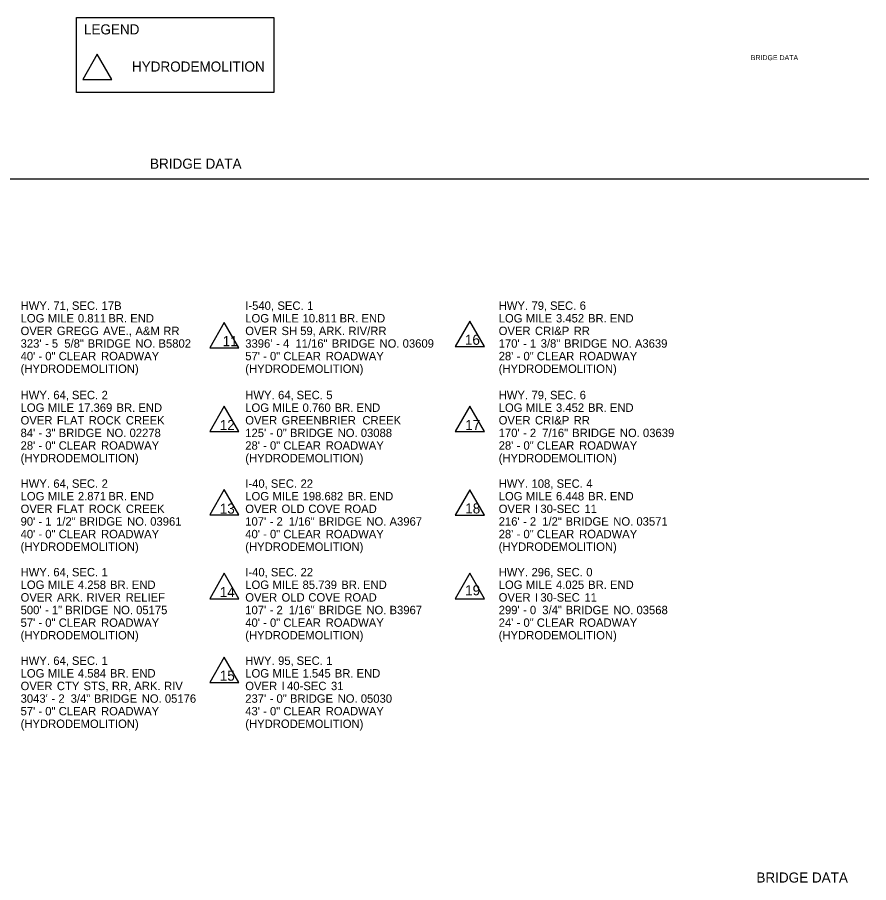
# Model space of a CAD drawing. Extents: x 1930579 to 1935271, y 596413 to 597442.
# Drawn here: x 1934259 to 1935271, y 596413 to 597442 of the extents above; entities that cross this region are included whole.
import ezdxf

# ---------------------------------------------------------------- set-up
doc = ezdxf.new("R2010")
doc.units = 0
for name, color, linetype in [('Default', 7, 'Continuous'), ('R_Border', 7, 'Continuous'), ('R_Border Prem', 7, 'Continuous')]:
    doc.layers.add(name, color=color, linetype=linetype)

msp = doc.modelspace()

# ---------------------------------------------------------------- linework, layer by layer
at = {"layer": 'R_Border'}
for p, q in [((1934353.7, 597398.8), (1934336.3, 597368.6)), ((1934371.1, 597368.6), (1934353.7, 597398.8)), ((1934336.3, 597368.6), (1934371.1, 597368.6)), ((1935270.8, 597250), (1933675.4, 597250)), ((1934504.7, 597079.6), (1934487.3, 597049.4)), ((1934522.1, 597049.4), (1934504.7, 597079.6)), ((1934796.4, 597081.3), (1934779, 597051.1)), ((1934813.9, 597051.1), (1934796.4, 597081.3)), ((1934487.3, 597049.4), (1934522.1, 597049.4)), ((1934779, 597051.1), (1934813.9, 597051.1)), ((1934504.7, 596980), (1934487.3, 596949.9)), ((1934522.1, 596949.9), (1934504.7, 596980)), ((1934796.4, 596980), (1934779, 596949.8)), ((1934813.9, 596949.8), (1934796.4, 596980)), ((1934487.3, 596949.9), (1934522.1, 596949.9)), ((1934779, 596949.8), (1934813.9, 596949.8)), ((1934504.7, 596880.8), (1934487.3, 596850.7)), ((1934522.1, 596850.7), (1934504.7, 596880.8)), ((1934796.4, 596880.7), (1934779, 596850.5)), ((1934813.9, 596850.5), (1934796.4, 596880.7)), ((1934487.3, 596850.7), (1934522.1, 596850.7)), ((1934779, 596850.5), (1934813.9, 596850.5)), ((1934504.7, 596781.3), (1934487.3, 596751.1)), ((1934522.1, 596751.1), (1934504.7, 596781.3)), ((1934796.4, 596781.3), (1934779, 596751.1)), ((1934813.9, 596751.1), (1934796.4, 596781.3)), ((1934487.3, 596751.1), (1934522.1, 596751.1)), ((1934779, 596751.1), (1934813.9, 596751.1)), ((1934504.7, 596681.8), (1934487.3, 596651.6)), ((1934522.1, 596651.6), (1934504.7, 596681.8)), ((1934487.3, 596651.6), (1934522.1, 596651.6))]:
    msp.add_line(p, q, dxfattribs=at)
msp.add_lwpolyline([(1934329, 597442.4), (1934563.4, 597442.4), (1934563.4, 597353.2), (1934329, 597353.2)], close=True, dxfattribs=at)

# ---------------------------------------------------------------- texts
at = {"layer": 'Default'}
for s, p in [('HWY.', (1934262.5, 597094.6)), (' 71,', (1934297.7, 597094.6)), (' SEC.', (1934319.8, 597094.6)), (' 17B', (1934355.1, 597094.6)), ('I-540,', (1934529.6, 597094.6)), (' SEC.', (1934564.1, 597094.6)), (' 1', (1934599.4, 597094.6)), ('HWY.', (1934830.9, 597094.6)), (' 79,', (1934866.2, 597094.6)), (' SEC.', (1934888.2, 597094.6)), (' 6', (1934923.5, 597094.6)), ('LOG', (1934262.5, 597079.6)), (' MILE', (1934291.1, 597079.6)), (' 0.811', (1934326.9, 597079.6)), (' BR.', (1934363.1, 597079.6)), (' END', (1934389.1, 597079.6)), ('LOG', (1934529.6, 597079.6)), (' MILE', (1934558.3, 597079.6)), (' 10.811', (1934594, 597079.6)), (' BR.', (1934638, 597079.6)), (' END', (1934664, 597079.6)), ('LOG', (1934830.9, 597079.6)), (' MILE', (1934859.5, 597079.6)), (' 3.452', (1934895.3, 597079.6)), (' BR.', (1934933.4, 597079.6)), (' END', (1934959.3, 597079.6)), ('OVER', (1934262.5, 597064.6)), (' GREGG', (1934301.9, 597064.6)), (' AVE.,', (1934356.9, 597064.6)), (' A&M', (1934395.3, 597064.6)), (' RR', (1934428.4, 597064.6)), ('OVER', (1934529.6, 597064.6)), (' SH', (1934569, 597064.6)), (' 59,', (1934591.2, 597064.6)), (' ARK.', (1934613.3, 597064.6)), (' RIV/RR', (1934648.5, 597064.6)), ('OVER', (1934830.9, 597064.6)), (' CRI&P', (1934870.3, 597064.6)), (' RR', (1934916.3, 597064.6)), ("323'", (1934262.5, 597049.6)), (' 5', (1934295.9, 597049.6)), ('  5/8"', (1934307, 597049.6)), (' BRIDGE', (1934338.5, 597049.6)), (' NO.', (1934395.2, 597049.6)), (' B5802', (1934422.7, 597049.6)), ("3396'", (1934529.6, 597049.6)), (' 4', (1934570.8, 597049.6)), ('  11/16"', (1934581.8, 597049.6)), (' BRIDGE', (1934628.8, 597049.6)), (' NO.', (1934685.5, 597049.6)), (' 03609', (1934713, 597049.6)), ("170'", (1934830.9, 597049.6)), (' 1', (1934864.3, 597049.6)), ('  3/8"', (1934873.4, 597049.6)), (' BRIDGE', (1934904.9, 597049.6)), (' NO.', (1934961.6, 597049.6)), (' A3639', (1934989.1, 597049.6)), (' -', (1934287.8, 597049.6)), (' -', (1934562.7, 597049.6)), (' -', (1934856.2, 597049.6)), ("40'", (1934262.5, 597034.6)), (' -', (1934280, 597034.6)), (' 0"', (1934288.1, 597034.6)), (' CLEAR', (1934304.1, 597034.6)), (' ROADWAY', (1934354.4, 597034.6)), ("57'", (1934529.6, 597034.6)), (' -', (1934547.2, 597034.6)), (' 0"', (1934555.3, 597034.6)), (' CLEAR', (1934571.2, 597034.6)), (' ROADWAY', (1934621.5, 597034.6)), ("28'", (1934830.9, 597034.6)), (' -', (1934848.5, 597034.6)), (' 0"', (1934856.6, 597034.6)), (' CLEAR', (1934872.5, 597034.6)), (' ROADWAY', (1934922.8, 597034.6)), ('(HYDRODEMOLITION)', (1934262.5, 597019.6)), ('(HYDRODEMOLITION)', (1934529.6, 597019.6)), ('(HYDRODEMOLITION)', (1934830.9, 597019.6)), ('HWY.', (1934262.5, 596988.3)), (' 64,', (1934297.7, 596988.3)), (' SEC.', (1934319.8, 596988.3)), (' 2', (1934355.1, 596988.3)), ('HWY.', (1934529.6, 596988.3)), (' 64,', (1934564.9, 596988.3)), (' SEC.', (1934586.9, 596988.3)), (' 5', (1934622.2, 596988.3)), ('HWY.', (1934830.9, 596988.3)), (' 79,', (1934866.2, 596988.3)), (' SEC.', (1934888.2, 596988.3)), (' 6', (1934923.5, 596988.3)), ('LOG', (1934262.5, 596973.3)), (' MILE', (1934291.1, 596973.3)), (' 17.369', (1934326.9, 596973.3)), (' BR.', (1934372.8, 596973.3)), (' END', (1934398.8, 596973.3)), ('LOG', (1934529.6, 596973.3)), (' MILE', (1934558.3, 596973.3)), (' 0.760', (1934594, 596973.3)), (' BR.', (1934632.2, 596973.3)), (' END', (1934658.1, 596973.3)), ('LOG', (1934830.9, 596973.3)), (' MILE', (1934859.5, 596973.3)), (' 3.452', (1934895.3, 596973.3)), (' BR.', (1934933.4, 596973.3)), (' END', (1934959.3, 596973.3)), ('OVER', (1934262.5, 596958.3)), (' FLAT', (1934301.9, 596958.3)), (' ROCK', (1934339.7, 596958.3)), (' CREEK', (1934383.9, 596958.3)), ('OVER', (1934529.6, 596958.3)), (' GREENBRIER', (1934569, 596958.3)), (' CREEK', (1934665.1, 596958.3)), ('OVER', (1934830.9, 596958.3)), (' CRI&P', (1934870.3, 596958.3)), (' RR', (1934916.3, 596958.3)), ("84'", (1934262.5, 596943.3)), (' -', (1934280, 596943.3)), (' 3"', (1934288.1, 596943.3)), (' BRIDGE', (1934304.1, 596943.3)), (' NO.', (1934360.8, 596943.3)), (' 02278', (1934388.3, 596943.3)), ("125'", (1934529.6, 596943.3)), (' -', (1934554.9, 596943.3)), (' 0"', (1934563, 596943.3)), (' BRIDGE', (1934579, 596943.3)), (' NO.', (1934635.7, 596943.3)), (' 03088', (1934663.2, 596943.3)), ("170'", (1934830.9, 596943.3)), (' -', (1934856.2, 596943.3)), (' 2', (1934864.3, 596943.3)), ('  7/16"', (1934875.2, 596943.3)), (' BRIDGE', (1934914.5, 596943.3)), (' NO.', (1934971.2, 596943.3)), (' 03639', (1934998.7, 596943.3)), ("28'", (1934262.5, 596928.3)), (' 0"', (1934288.1, 596928.3)), (' CLEAR', (1934304.1, 596928.3)), (' ROADWAY', (1934354.4, 596928.3)), ("28'", (1934529.6, 596928.3)), (' 0"', (1934555.3, 596928.3)), (' CLEAR', (1934571.2, 596928.3)), (' ROADWAY', (1934621.5, 596928.3)), ("28'", (1934830.9, 596928.3)), (' 0"', (1934856.6, 596928.3)), (' CLEAR', (1934872.5, 596928.3)), (' ROADWAY', (1934922.8, 596928.3)), (' -', (1934280, 596928.3)), (' -', (1934547.2, 596928.3)), (' -', (1934848.5, 596928.3)), ('(HYDRODEMOLITION)', (1934262.5, 596913.3)), ('(HYDRODEMOLITION)', (1934529.6, 596913.3)), ('(HYDRODEMOLITION)', (1934830.9, 596913.3)), ('HWY.', (1934262.5, 596883)), (' 64,', (1934297.7, 596883)), (' SEC.', (1934319.8, 596883)), (' 2', (1934355.1, 596883)), ('I-40,', (1934529.6, 596883)), (' SEC.', (1934556.3, 596883)), (' 22', (1934591.6, 596883)), ('HWY.', (1934830.9, 596883)), (' 108,', (1934866.2, 596883)), (' SEC.', (1934896, 596883)), (' 4', (1934931.3, 596883)), ('LOG', (1934262.5, 596868)), (' MILE', (1934291.1, 596868)), (' 2.871', (1934326.9, 596868)), (' BR.', (1934363.1, 596868)), (' END', (1934389.1, 596868)), ('LOG', (1934529.6, 596868)), (' MILE', (1934558.3, 596868)), (' 198.682', (1934594, 596868)), (' BR.', (1934647.6, 596868)), (' END', (1934673.6, 596868)), ('LOG', (1934830.9, 596868)), (' MILE', (1934859.5, 596868)), (' 6.448', (1934895.3, 596868)), (' BR.', (1934933.5, 596868)), (' END', (1934959.4, 596868)), ('OVER', (1934262.5, 596853)), (' FLAT', (1934301.9, 596853)), (' ROCK', (1934339.7, 596853)), (' CREEK', (1934383.9, 596853)), ('OVER', (1934529.6, 596853)), (' OLD', (1934569, 596853)), (' COVE', (1934600.9, 596853)), (' ROAD', (1934643.6, 596853)), ('OVER', (1934830.9, 596853)), (' I', (1934870.3, 596853)), (' 30-SEC', (1934876.8, 596853)), (' 11', (1934929.1, 596853)), ("90'", (1934262.5, 596838)), (' -', (1934280, 596838)), (' 1', (1934288.1, 596838)), ('  1/2"', (1934297.2, 596838)), (' BRIDGE', (1934328.7, 596838)), (' NO.', (1934385.4, 596838)), (' 03961', (1934412.9, 596838)), ("107'", (1934529.6, 596838)), (' -', (1934554.9, 596838)), (' 2', (1934563, 596838)), ('  1/16"', (1934573.9, 596838)), (' BRIDGE', (1934613.2, 596838)), (' NO.', (1934669.9, 596838)), (' A3967', (1934697.4, 596838)), ("216'", (1934830.9, 596838)), (' -', (1934856.2, 596838)), (' 2', (1934864.3, 596838)), ('  1/2"', (1934875.2, 596838)), (' BRIDGE', (1934906.7, 596838)), (' NO.', (1934963.4, 596838)), (' 03571', (1934990.9, 596838)), ("40'", (1934262.5, 596823)), (' 0"', (1934288.1, 596823)), (' CLEAR', (1934304.1, 596823)), (' ROADWAY', (1934354.4, 596823)), ("40'", (1934529.6, 596823)), (' 0"', (1934555.3, 596823)), (' CLEAR', (1934571.2, 596823)), (' ROADWAY', (1934621.5, 596823)), ("28'", (1934830.9, 596823)), (' 0"', (1934856.6, 596823)), (' CLEAR', (1934872.5, 596823)), (' ROADWAY', (1934922.8, 596823)), (' -', (1934280, 596823)), (' -', (1934547.2, 596823)), (' -', (1934848.5, 596823)), ('(HYDRODEMOLITION)', (1934262.5, 596808)), ('(HYDRODEMOLITION)', (1934529.6, 596808)), ('(HYDRODEMOLITION)', (1934830.9, 596808)), ('HWY.', (1934262.5, 596777.7)), (' 64,', (1934297.7, 596777.7)), (' SEC.', (1934319.8, 596777.7)), (' 1', (1934355.1, 596777.7)), ('I-40,', (1934529.6, 596777.7)), (' SEC.', (1934556.3, 596777.7)), (' 22', (1934591.6, 596777.7)), ('HWY.', (1934830.9, 596777.7)), (' 296,', (1934866.2, 596777.7)), (' SEC.', (1934896, 596777.7)), (' 0', (1934931.3, 596777.7)), ('LOG', (1934262.5, 596762.7)), (' MILE', (1934291.1, 596762.7)), (' 4.258', (1934326.9, 596762.7)), (' BR.', (1934365.1, 596762.7)), (' END', (1934391, 596762.7)), ('LOG', (1934529.6, 596762.7)), (' MILE', (1934558.3, 596762.7)), (' 85.739', (1934594, 596762.7)), (' BR.', (1934640, 596762.7)), (' END', (1934665.9, 596762.7)), ('LOG', (1934830.9, 596762.7)), (' MILE', (1934859.5, 596762.7)), (' 4.025', (1934895.3, 596762.7)), (' BR.', (1934933.5, 596762.7)), (' END', (1934959.5, 596762.7)), ('OVER', (1934262.5, 596747.7)), (' ARK.', (1934301.9, 596747.7)), (' RIVER', (1934337.2, 596747.7)), (' RELIEF', (1934383.6, 596747.7)), ('OVER', (1934529.6, 596747.7)), (' OLD', (1934569, 596747.7)), (' COVE', (1934600.9, 596747.7)), (' ROAD', (1934643.6, 596747.7)), ('OVER', (1934830.9, 596747.7)), (' I', (1934870.3, 596747.7)), (' 30-SEC', (1934876.8, 596747.7)), (' 11', (1934929.1, 596747.7)), ("500'", (1934262.5, 596732.7)), (' 1"', (1934295.9, 596732.7)), (' BRIDGE', (1934311.8, 596732.7)), (' NO.', (1934368.6, 596732.7)), (' 05175', (1934396.1, 596732.7)), ("107'", (1934529.6, 596732.7)), (' 2', (1934563, 596732.7)), ('  1/16"', (1934573.9, 596732.7)), (' BRIDGE', (1934613.2, 596732.7)), (' NO.', (1934669.9, 596732.7)), (' B3967', (1934697.4, 596732.7)), ("299'", (1934830.9, 596732.7)), (' 0', (1934864.3, 596732.7)), ('  3/4"', (1934875.3, 596732.7)), (' BRIDGE', (1934906.8, 596732.7)), (' NO.', (1934963.5, 596732.7)), (' 03568', (1934991, 596732.7)), (' -', (1934287.8, 596732.7)), (' -', (1934554.9, 596732.7)), (' -', (1934856.2, 596732.7)), ("57'", (1934262.5, 596717.7)), (' -', (1934280, 596717.7)), (' 0"', (1934288.1, 596717.7)), (' CLEAR', (1934304.1, 596717.7)), (' ROADWAY', (1934354.4, 596717.7)), ("40'", (1934529.6, 596717.7)), (' -', (1934547.2, 596717.7)), (' 0"', (1934555.3, 596717.7)), (' CLEAR', (1934571.2, 596717.7)), (' ROADWAY', (1934621.5, 596717.7)), ("24'", (1934830.9, 596717.7)), (' -', (1934848.5, 596717.7)), (' 0"', (1934856.6, 596717.7)), (' CLEAR', (1934872.5, 596717.7)), (' ROADWAY', (1934922.8, 596717.7)), ('(HYDRODEMOLITION)', (1934262.5, 596702.7)), ('(HYDRODEMOLITION)', (1934529.6, 596702.7)), ('(HYDRODEMOLITION)', (1934830.9, 596702.7)), ('HWY.', (1934262.5, 596672.4)), (' 64,', (1934297.7, 596672.4)), (' SEC.', (1934319.8, 596672.4)), (' 1', (1934355.1, 596672.4)), ('HWY.', (1934529.6, 596672.4)), (' 95,', (1934564.9, 596672.4)), (' SEC.', (1934586.9, 596672.4)), (' 1', (1934622.2, 596672.4)), ('LOG', (1934262.5, 596657.4)), (' MILE', (1934291.1, 596657.4)), (' 4.584', (1934326.9, 596657.4)), (' BR.', (1934365, 596657.4)), (' END', (1934391, 596657.4)), ('LOG', (1934529.6, 596657.4)), (' MILE', (1934558.3, 596657.4)), (' 1.545', (1934594, 596657.4)), (' BR.', (1934632.3, 596657.4)), (' END', (1934658.2, 596657.4)), ('OVER', (1934262.5, 596642.4)), (' CTY', (1934301.9, 596642.4)), (' STS,', (1934333.6, 596642.4)), (' RR,', (1934367.3, 596642.4)), (' ARK.', (1934394, 596642.4)), (' RIV', (1934429.3, 596642.4)), ('OVER', (1934529.6, 596642.4)), (' I', (1934569, 596642.4)), (' 40-SEC', (1934575.6, 596642.4)), (' 31', (1934627.8, 596642.4)), ("3043'", (1934262.5, 596627.4)), (' 2', (1934303.7, 596627.4)), ('  3/4"', (1934314.6, 596627.4)), (' BRIDGE', (1934346, 596627.4)), (' NO.', (1934402.8, 596627.4)), (' 05176', (1934430.3, 596627.4)), ("237'", (1934529.6, 596627.4)), (' 0"', (1934563, 596627.4)), (' BRIDGE', (1934579, 596627.4)), (' NO.', (1934635.7, 596627.4)), (' 05030', (1934663.2, 596627.4)), (' -', (1934295.6, 596627.4)), (' -', (1934554.9, 596627.4)), ("57'", (1934262.5, 596612.4)), (' -', (1934280, 596612.4)), (' 0"', (1934288.1, 596612.4)), (' CLEAR', (1934304.1, 596612.4)), (' ROADWAY', (1934354.4, 596612.4)), ("43'", (1934529.6, 596612.4)), (' -', (1934547.2, 596612.4)), (' 0"', (1934555.3, 596612.4)), (' CLEAR', (1934571.2, 596612.4)), (' ROADWAY', (1934621.5, 596612.4)), ('(HYDRODEMOLITION)', (1934262.5, 596597.4)), ('(HYDRODEMOLITION)', (1934529.6, 596597.4))]:
    msp.add_text(s, height=10, rotation=360, dxfattribs=at).set_placement(p)
at = {"layer": 'R_Border'}
for s, p in [('LEGEND', (1934337.8, 597422.1)), ('HYDRODEMOLITION', (1934394.9, 597377.9)), ('BRIDGE DATA', (1934416.4, 597262.4)), ('11', (1934502.7, 597051.4)), ('16', (1934790.7, 597053)), ('12', (1934499.3, 596951.6)), ('17', (1934791.1, 596951.7)), ('13', (1934499.3, 596852.3)), ('18', (1934791.1, 596852.5)), ('14', (1934499.3, 596753)), ('19', (1934791, 596755.2)), ('15', (1934499.3, 596653.6)), ('BRIDGE DATA', (1935137.3, 596413.6))]:
    msp.add_text(s, height=12, rotation=360, dxfattribs=at).set_placement(p)
at = {"layer": 'R_Border Prem'}
msp.add_text('BRIDGE DATA', height=6, rotation=360, dxfattribs=at).set_placement((1935130.7, 597391.5))

doc.saveas('drawing.dxf')
